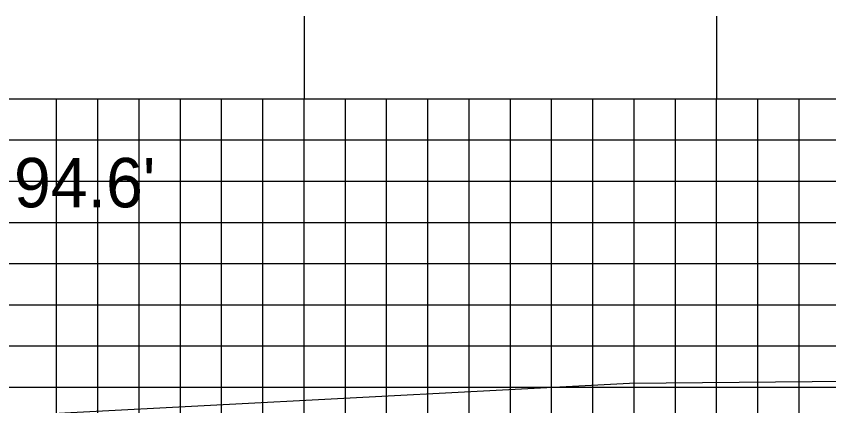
# Model space of a CAD drawing. Extents: x 1769661 to 1770005, y 442591 to 442811.
# Drawn here: x 1769730.04 to 1769749.73, y 442651.21 to 442660.67 of the extents above; entities that cross this region are included whole.
import ezdxf

# ---------------------------------------------------------------- set-up
doc = ezdxf.new("R2010")
doc.units = 0
for name, color, linetype in [('D_Text_Standard', 7, 'Continuous'), ('MAJOR', 7, 'Continuous'), ('MINOR', 7, 'Continuous'), ('S_Roadway_Centerline', 7, 'Continuous')]:
    doc.layers.add(name, color=color, linetype=linetype)

msp = doc.modelspace()

# ---------------------------------------------------------------- linework, layer by layer
at = {"layer": 'MAJOR'}
for p, q in [((1769737.015, 442660.669), (1769737.015, 442658.665)), ((1769747.015, 442660.669), (1769747.015, 442658.665)), ((1769687.015, 442658.665), (1769967.015, 442658.665)), ((1769687.015, 442658.665), (1769967.015, 442658.665)), ((1769737.015, 442608.665), (1769737.015, 442658.665)), ((1769747.015, 442608.665), (1769747.015, 442658.665)), ((1769687.015, 442653.665), (1769967.015, 442653.665))]:
    msp.add_line(p, q, dxfattribs=at)
at = {"layer": 'MINOR'}
for p, q in [((1769731.015, 442608.665), (1769731.015, 442658.665)), ((1769732.015, 442608.665), (1769732.015, 442658.665)), ((1769733.015, 442608.665), (1769733.015, 442658.665)), ((1769734.015, 442608.665), (1769734.015, 442658.665)), ((1769735.015, 442608.665), (1769735.015, 442658.665)), ((1769736.015, 442608.665), (1769736.015, 442658.665)), ((1769738.015, 442608.665), (1769738.015, 442658.665)), ((1769739.015, 442608.665), (1769739.015, 442658.665)), ((1769740.015, 442608.665), (1769740.015, 442658.665)), ((1769741.015, 442608.665), (1769741.015, 442658.665)), ((1769742.015, 442608.665), (1769742.015, 442658.665)), ((1769743.015, 442608.665), (1769743.015, 442658.665)), ((1769744.015, 442608.665), (1769744.015, 442658.665)), ((1769745.015, 442608.665), (1769745.015, 442658.665)), ((1769746.015, 442608.665), (1769746.015, 442658.665)), ((1769748.015, 442608.665), (1769748.015, 442658.665)), ((1769749.015, 442608.665), (1769749.015, 442658.665)), ((1769687.015, 442657.665), (1769967.015, 442657.665)), ((1769687.015, 442656.665), (1769967.015, 442656.665)), ((1769687.015, 442655.665), (1769967.015, 442655.665)), ((1769687.015, 442654.665), (1769967.015, 442654.665)), ((1769687.015, 442652.665), (1769967.015, 442652.665)), ((1769687.015, 442651.665), (1769967.015, 442651.665))]:
    msp.add_line(p, q, dxfattribs=at)
at = {"layer": 'S_Roadway_Centerline'}
msp.add_lwpolyline([(1769687.015, 442649.293), (1769687.167, 442649.298), (1769704.645, 442650.096), (1769707.209, 442650.162), (1769716.906, 442650.478), (1769725.648, 442650.726), (1769731.355, 442651.044), (1769744.901, 442651.762), (1769762.614, 442651.923), (1769763.542, 442651.932), (1769764.174, 442651.952), (1769766.643, 442651.943), (1769783.404, 442652.101), (1769793.271, 442652.323), (1769802.466, 442652.537), (1769810.991, 442652.523), (1769822.479, 442652.429), (1769825.284, 442652.418), (1769840.906, 442652.283), (1769846.533, 442651.967), (1769855.905, 442652.007), (1769858.8, 442652.029)], dxfattribs=at)

# ---------------------------------------------------------------- texts
at = {"layer": 'D_Text_Standard'}
msp.add_text("94.6'", height=1.2, dxfattribs=at).set_placement((1769729.981, 442656.029))

doc.saveas('drawing.dxf')
